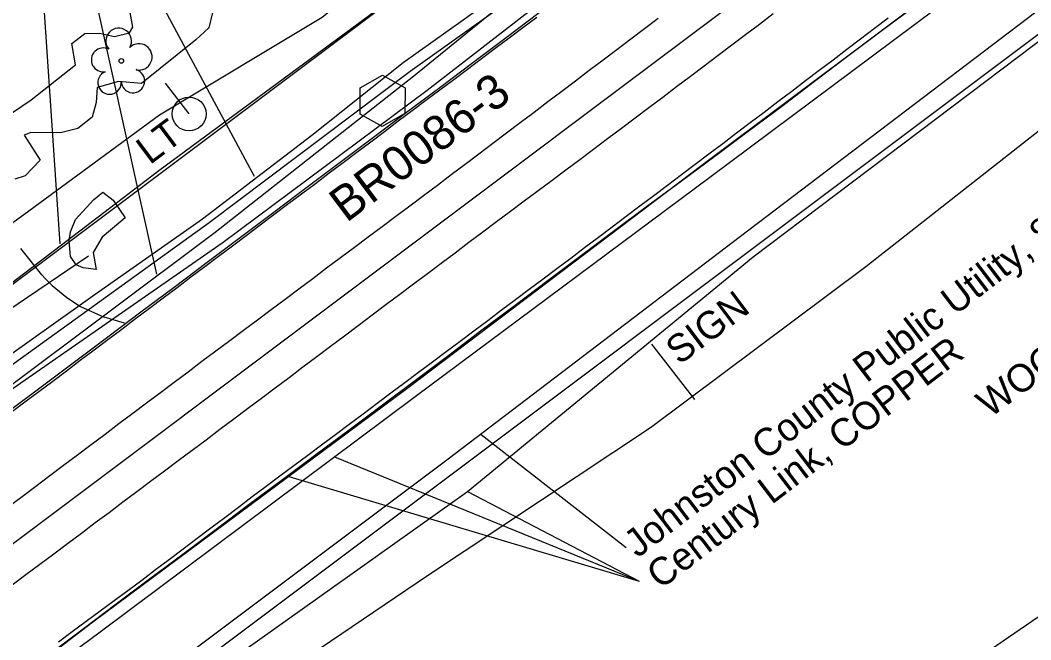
# Model space of a CAD drawing. Extents: x 2186615 to 2188822, y 629899 to 631820.
# Drawn here: x 2188283 to 2188429.1, y 631223.1 to 631312.5 of the extents above; entities that cross this region are included whole.
import ezdxf

# ---------------------------------------------------------------- set-up
doc = ezdxf.new("R2010")
doc.units = 0
for name, color, linetype in [('CTL Primary Horizontal and Vertical CELL', 7, 'Continuous'), ('CTL Primary Horizontal and Vertical Text', 7, 'Continuous'), ('Exist Horizontal Alignment', 7, 'Continuous'), ('Exist Other Culture Area Outline', 7, 'Continuous'), ('Exist Other Culture Sign', 7, 'Continuous'), ('Exist Other Culture Sign Text', 7, 'Continuous'), ('Exist Right of Way Line', 7, 'Continuous'), ('Exist Roads EOP', 7, 'Continuous'), ('Exist Roads EOT', 7, 'Continuous'), ('Exist Roads Soil', 7, 'Continuous'), ('Exist Structure Minor Pipes RCP 18 Inch', 7, 'Continuous'), ('Exist Utilities Gas UG Line SUE LOS B', 7, 'Continuous'), ('Exist Utilities Gas UG Line SUE LOS B Leader', 7, 'Continuous'), ('Exist Utilities Power Pole CELL', 7, 'Continuous'), ('Exist Utilities Power Pole Text', 7, 'Continuous'), ('Exist Utilities Sanitary Sewer Forced Main SUE LOS B', 7, 'Continuous'), ('Exist Utilities Sanitary Sewer Forced Main SUE LOS B Leader', 7, 'Continuous'), ('Exist Utilities Sanitary Sewer Forced Main SUE LOS B Text', 7, 'Continuous'), ('Exist Utilities Telephone UG Cable SUE LOS C', 7, 'Continuous'), ('Exist Utilities Telephone UG Cable SUE LOS C Leader', 7, 'Continuous'), ('Exist Utilities Telephone UG Cable SUE LOS C Text', 7, 'Continuous'), ('Exist Utilities Telephone UG FO SUE LOS B', 7, 'Continuous'), ('Exist Utilities Telephone UG FO SUE LOS B Leader', 7, 'Continuous'), ('Exist Utilities Water UG Line SUE LOS B', 7, 'Continuous'), ('Exist Utilities Water UG Line SUE LOS B Leader', 7, 'Continuous'), ('Exist Vegetation Hedge Row', 7, 'Continuous'), ('Exist Vegetation Tree CELL', 7, 'Continuous'), ('Exist Vegetation Woods Line', 7, 'Continuous'), ('Exist Vegetation Woods Line Text', 7, 'Continuous')]:
    doc.layers.add(name, color=color, linetype=linetype)

msp = doc.modelspace()

# ---------------------------------------------------------------- linework, layer by layer
at = {"layer": 'CTL Primary Horizontal and Vertical CELL'}
msp.add_line((2188335.41, 631300.89), (2188335.41, 631300.89), dxfattribs=at)
msp.add_lwpolyline([(2188332.17, 631302.76), (2188335.42, 631304.58), (2188338.67, 631302.79), (2188338.62, 631299.06), (2188335.37, 631297.18), (2188332.17, 631298.99)], close=True, dxfattribs=at)
at = {"layer": 'Exist Horizontal Alignment'}
msp.add_line((2187136.41, 630378.11), (2188520.86, 631416.04), dxfattribs=at)
at = {"layer": 'Exist Other Culture Area Outline'}
msp.add_lwpolyline([(2188291.05, 631283.75), (2188293.63, 631286.62), (2188295, 631287.71), (2188296.46, 631286.56), (2188298.22, 631283.98), (2188294.91, 631281.2), (2188293.6, 631278.98), (2188294.02, 631276.56), (2188292.16, 631276.76), (2188291.14, 631277.22), (2188290.31, 631278.41), (2188290.14, 631280.66), (2188290.34, 631282), (2188291.05, 631283.75)], dxfattribs=at)
at = {"layer": 'Exist Other Culture Sign'}
msp.add_line((2188374.26, 631265.78), (2188380.47, 631257.75), dxfattribs=at)
at = {"layer": 'Exist Right of Way Line'}
for p, q in [((2187118.41, 630402.11), (2188502.83, 631440.02)), ((2187154.4, 630354.1), (2188538.85, 631392.04))]:
    msp.add_line(p, q, dxfattribs=at)
at = {"layer": 'Exist Roads EOP'}
for points in [[(2188281.29, 631256.01), (2188286.1, 631259.61), (2188290.9, 631263.21), (2188295.7, 631266.81), (2188300.49, 631270.41), (2188305.29, 631274.01), (2188310.09, 631277.62), (2188314.89, 631281.22), (2188319.68, 631284.82), (2188324.48, 631288.43), (2188329.28, 631292.03), (2188334.08, 631295.63), (2188338.87, 631299.24), (2188343.67, 631302.84), (2188348.47, 631306.45), (2188353.26, 631310.05), (2188358.05, 631313.67), (2188362.84, 631317.28), (2188367.63, 631320.9), (2188372.41, 631324.51), (2188377.2, 631328.13), (2188381.99, 631331.74), (2188386.8, 631335.34), (2188391.5, 631338.86)], [(2188412.22, 631314.48), (2188407.4, 631310.9), (2188402.59, 631307.32), (2188397.82, 631303.68), (2188393.07, 631300.02), (2188388.25, 631296.45), (2188383.43, 631292.88), (2188378.6, 631289.31), (2188373.77, 631285.75), (2188368.96, 631282.16), (2188364.16, 631278.56), (2188359.36, 631274.96), (2188354.56, 631271.36), (2188349.77, 631267.76), (2188344.98, 631264.14), (2188340.19, 631260.53), (2188335.39, 631256.93), (2188330.58, 631253.34), (2188325.77, 631249.76), (2188320.96, 631246.17), (2188316.16, 631242.58), (2188311.35, 631238.99), (2188306.54, 631235.4), (2188301.74, 631231.8), (2188296.93, 631228.21), (2188292.13, 631224.61), (2188287.34, 631221)]]:
    msp.add_lwpolyline(points, dxfattribs=at)
at = {"layer": 'Exist Roads EOT'}
for points in [[(2188281.33, 631242.27), (2188283.32, 631243.77), (2188285.32, 631245.27), (2188287.32, 631246.77), (2188289.32, 631248.27), (2188291.32, 631249.77), (2188293.32, 631251.28), (2188295.32, 631252.78), (2188297.32, 631254.28), (2188299.32, 631255.78), (2188301.32, 631257.28), (2188303.32, 631258.78), (2188305.31, 631260.28), (2188307.31, 631261.78), (2188309.32, 631263.28), (2188311.32, 631264.78), (2188313.32, 631266.28), (2188315.32, 631267.77), (2188317.32, 631269.27), (2188319.32, 631270.77), (2188321.33, 631272.26), (2188323.33, 631273.76), (2188325.33, 631275.26), (2188327.33, 631276.76), (2188329.34, 631278.25), (2188331.34, 631279.75), (2188333.34, 631281.25), (2188335.34, 631282.75), (2188337.34, 631284.24), (2188339.34, 631285.74), (2188341.35, 631287.24), (2188343.35, 631288.74), (2188345.34, 631290.24), (2188347.34, 631291.75), (2188349.33, 631293.26), (2188351.33, 631294.76), (2188353.32, 631296.27), (2188355.32, 631297.78), (2188357.31, 631299.28), (2188359.31, 631300.79), (2188361.3, 631302.3), (2188363.3, 631303.8), (2188365.29, 631305.31), (2188367.28, 631306.82), (2188369.28, 631308.33), (2188371.27, 631309.83), (2188373.27, 631311.34), (2188375.26, 631312.84)], [(2188281.74, 631255.92), (2188283.74, 631257.43), (2188285.74, 631258.93), (2188287.74, 631260.43), (2188289.73, 631261.93), (2188291.73, 631263.44), (2188293.73, 631264.94), (2188295.73, 631266.44), (2188297.73, 631267.94), (2188299.72, 631269.45), (2188301.72, 631270.95), (2188303.72, 631272.45), (2188305.72, 631273.95), (2188307.72, 631275.46), (2188309.71, 631276.96), (2188311.71, 631278.46), (2188313.71, 631279.96), (2188315.71, 631281.46), (2188317.71, 631282.97), (2188319.71, 631284.47), (2188321.7, 631285.97), (2188323.7, 631287.47), (2188325.7, 631288.97), (2188327.7, 631290.48), (2188329.7, 631291.98), (2188331.7, 631293.48), (2188333.7, 631294.98), (2188335.69, 631296.48), (2188337.69, 631297.99), (2188339.69, 631299.49), (2188341.69, 631300.99), (2188343.69, 631302.49), (2188345.69, 631303.99), (2188347.69, 631305.49), (2188349.69, 631306.99), (2188351.69, 631308.49), (2188353.69, 631309.99), (2188355.69, 631311.49), (2188357.69, 631312.99)], [(2188281.88, 631230.99), (2188283.88, 631232.49), (2188285.88, 631233.99), (2188287.89, 631235.48), (2188289.89, 631236.98), (2188291.89, 631238.48), (2188293.89, 631239.98), (2188295.89, 631241.47), (2188297.89, 631242.97), (2188299.9, 631244.47), (2188301.9, 631245.97), (2188303.9, 631247.47), (2188305.9, 631248.96), (2188307.9, 631250.46), (2188309.9, 631251.96), (2188311.9, 631253.46), (2188313.91, 631254.96), (2188315.91, 631256.45), (2188317.91, 631257.96), (2188319.9, 631259.46), (2188321.9, 631260.96), (2188323.9, 631262.46), (2188325.9, 631263.96), (2188327.9, 631265.46), (2188329.9, 631266.97), (2188331.9, 631268.47), (2188333.89, 631269.97), (2188335.89, 631271.47), (2188337.89, 631272.97), (2188339.89, 631274.48), (2188341.89, 631275.98), (2188343.89, 631277.47), (2188345.89, 631278.97), (2188347.89, 631280.47), (2188349.9, 631281.96), (2188351.9, 631283.46), (2188353.9, 631284.96), (2188355.9, 631286.46), (2188357.91, 631287.95), (2188359.91, 631289.45), (2188361.91, 631290.95), (2188363.91, 631292.44), (2188365.92, 631293.94), (2188367.92, 631295.44), (2188369.92, 631296.94), (2188371.92, 631298.44), (2188373.91, 631299.94), (2188375.91, 631301.45), (2188377.9, 631302.96), (2188379.9, 631304.46), (2188381.89, 631305.97), (2188383.89, 631307.47), (2188385.89, 631308.98), (2188387.88, 631310.48), (2188389.88, 631311.99), (2188391.87, 631313.49)], [(2188408.48, 631312.83), (2188406.49, 631311.32), (2188404.5, 631309.81), (2188402.5, 631308.3), (2188400.51, 631306.79), (2188398.52, 631305.28), (2188396.53, 631303.77), (2188394.54, 631302.26), (2188392.55, 631300.74), (2188390.56, 631299.23), (2188388.56, 631297.72), (2188386.57, 631296.22), (2188384.57, 631294.71), (2188382.58, 631293.21), (2188380.58, 631291.7), (2188378.59, 631290.2), (2188376.59, 631288.69), (2188374.6, 631287.18), (2188372.6, 631285.68), (2188370.6, 631284.17), (2188368.61, 631282.67), (2188366.61, 631281.16), (2188364.62, 631279.66), (2188362.62, 631278.15), (2188360.62, 631276.65), (2188358.62, 631275.15), (2188356.62, 631273.65), (2188354.62, 631272.15), (2188352.62, 631270.65), (2188350.62, 631269.15), (2188348.62, 631267.65), (2188346.62, 631266.15), (2188344.62, 631264.65), (2188342.62, 631263.15), (2188340.62, 631261.65), (2188338.62, 631260.16), (2188336.61, 631258.66), (2188334.61, 631257.17), (2188332.61, 631255.67), (2188330.6, 631254.17), (2188328.6, 631252.68), (2188326.6, 631251.18), (2188324.6, 631249.69), (2188322.59, 631248.19), (2188320.59, 631246.69), (2188318.59, 631245.19), (2188316.59, 631243.69), (2188314.6, 631242.19), (2188312.6, 631240.68), (2188310.61, 631239.17), (2188308.61, 631237.67), (2188306.62, 631236.16), (2188304.62, 631234.65), (2188302.62, 631233.15), (2188300.63, 631231.65), (2188298.62, 631230.16), (2188296.61, 631228.67), (2188294.6, 631227.18), (2188292.59, 631225.7), (2188290.58, 631224.21), (2188288.57, 631222.72)]]:
    msp.add_lwpolyline(points, dxfattribs=at)
at = {"layer": 'Exist Roads Soil'}
for points in [[(2188286.65, 631275.23), (2188286.18, 631275.75), (2188283.12, 631279.56)], [(2188286.65, 631275.23), (2188287.68, 631274.25), (2188289.79, 631272.52), (2188291.78, 631271.19), (2188295.18, 631269.64)], [(2188298.13, 631268.79), (2188295.18, 631269.64)]]:
    msp.add_lwpolyline(points, dxfattribs=at)
at = {"layer": 'Exist Structure Minor Pipes RCP 18 Inch'}
msp.add_line((2188232.7, 631237.84), (2188292.92, 631278.53), dxfattribs=at)
at = {"layer": 'Exist Utilities Gas UG Line SUE LOS B'}
msp.add_lwpolyline([(2188219.39, 631219.84), (2188231.62, 631228.2), (2188246.17, 631238.93), (2188255.42, 631245.33), (2188268.48, 631254.78), (2188278.59, 631262.16), (2188293.89, 631272.96), (2188309.4, 631283.84), (2188325.21, 631295.95), (2188338.4, 631306.43), (2188349.22, 631314.15), (2188361.2, 631323.18), (2188372.45, 631332.07), (2188381.36, 631339.98), (2188392.05, 631352.12), (2188396.89, 631358.2), (2188400.9, 631362.5), (2188409.32, 631368.76), (2188417.18, 631375.21), (2188429.81, 631386.38)], dxfattribs=at)
at = {"layer": 'Exist Utilities Gas UG Line SUE LOS B Leader'}
msp.add_line((2188316.89, 631289.98), (2188292.6, 631335.2), dxfattribs=at)
at = {"layer": 'Exist Utilities Power Pole CELL'}
for q in [(2188304.05, 631303.47), (2188307.45, 631299)]:
    msp.add_line((2188307.45, 631299), q, dxfattribs=at)
msp.add_circle((2188307.45, 631299), 2.45, dxfattribs=at)
at = {"layer": 'Exist Utilities Sanitary Sewer Forced Main SUE LOS B'}
msp.add_lwpolyline([(2188052.08, 631035.89), (2188074.5, 631052.61), (2188093.79, 631066.37), (2188121.43, 631086.62), (2188146.17, 631105.29), (2188183, 631130.32), (2188212.25, 631151.9), (2188236.06, 631169.55), (2188274.9, 631197.79), (2188300.59, 631215.98), (2188344.72, 631249.04), (2188387.13, 631281.33), (2188437.44, 631319.58), (2188480.75, 631351.94), (2188530.77, 631388.8), (2188537.37, 631394.07)], dxfattribs=at)
at = {"layer": 'Exist Utilities Sanitary Sewer Forced Main SUE LOS B Leader'}
msp.add_line((2188349.66, 631252.69), (2188370.64, 631236.4), dxfattribs=at)
at = {"layer": 'Exist Utilities Telephone UG Cable SUE LOS C'}
for points in [[(2188096.88, 630993.34), (2188080.22, 631017.51), (2188064.37, 631042.87), (2188062.98, 631045.24), (2188062.65, 631047.71), (2188067.09, 631054.3), (2188068.63, 631056.84), (2188089.09, 631072.74), (2188116.44, 631092.81), (2188141.03, 631110.94), (2188178.22, 631138.01), (2188229.96, 631175.9), (2188269.4, 631205.59), (2188294.58, 631224.2), (2188340.11, 631258.2), (2188382.72, 631289.85), (2188432.93, 631327.36), (2188477.32, 631360.56), (2188524.82, 631398.08), (2188530.94, 631402.62)], [(2188239.88, 631089.23), (2188209.7, 631139.17), (2188205.31, 631145.33), (2188202.92, 631147.6), (2188200.81, 631153.01), (2188202.37, 631156.1), (2188209.69, 631162.82), (2188228.85, 631177.06), (2188268.68, 631206.68), (2188293.54, 631225.66), (2188339.11, 631259.48), (2188381.57, 631291.6), (2188431.82, 631329.3), (2188475.74, 631362.76), (2188523.99, 631399.21), (2188530.06, 631403.8)], [(2188312.37, 631280.51), (2188341.87, 631302.43), (2188368.35, 631323.01), (2188385.25, 631335.41), (2188398.42, 631345.26), (2188424.55, 631364.83), (2188476.35, 631403.47)], [(2188094.37, 630991.41), (2188096.88, 630993.34), (2188087.79, 631026.43), (2188086.82, 631054.16), (2188087.06, 631058.84), (2188088.93, 631062.35), (2188093.27, 631066.84), (2188121.22, 631086.85), (2188145.88, 631105.9), (2188182.55, 631131.21), (2188212.13, 631152.41), (2188236.63, 631168.55), (2188279.23, 631192.06), (2188292.43, 631201.57), (2188302.49, 631212.36), (2188347.67, 631244.49), (2188388.98, 631278.39), (2188439.32, 631316.4), (2188482.92, 631349.33), (2188532.32, 631387.1), (2188539.16, 631391.7)], [(2188310.34, 631283.34), (2188339.41, 631305.19), (2188367.17, 631324.97), (2188382.91, 631337.59), (2188408.07, 631361.6)], [(2188214.19, 631233.71), (2188214.21, 631236.64), (2188215.1, 631239.68), (2188225.32, 631247.53), (2188241.06, 631256.41), (2188259.35, 631266.95), (2188283.55, 631284.49), (2188303.17, 631298.86), (2188326.67, 631313), (2188359.63, 631339.91)], [(2188214.19, 631233.71), (2188224.61, 631226.53), (2188230.77, 631229.27), (2188255.03, 631245.94), (2188279.19, 631260.88), (2188310.34, 631283.34)], [(2188214.19, 631233.71), (2188223.22, 631223.19), (2188223.22, 631223.19), (2188232.86, 631227.26), (2188257.42, 631242.88), (2188270.4, 631252.69), (2188280.92, 631258.65), (2188312.37, 631280.51)]]:
    msp.add_lwpolyline(points, dxfattribs=at)
at = {"layer": 'Exist Utilities Telephone UG Cable SUE LOS C Leader'}
for p in [(2188328.49, 631249.49), (2188321.85, 631246.64), (2188347.67, 631244.49)]:
    msp.add_line(p, (2188372.5, 631231.51), dxfattribs=at)
at = {"layer": 'Exist Utilities Telephone UG FO SUE LOS B'}
for points in [[(2188303.07, 631290.83), (2188335.53, 631314.77), (2188356.73, 631330.39), (2188376.84, 631345.11), (2188395.22, 631359.35), (2188416.54, 631375.89), (2188457.16, 631405.12)], [(2187859.07, 630951.55), (2187882.76, 630968.07), (2187903.06, 630983.05), (2187928.09, 631001.38), (2187948.02, 631018.93), (2187983.82, 631042.28), (2188016.23, 631068.08), (2188049.6, 631091.76), (2188063.06, 631102.31), (2188071.06, 631108.58), (2188069.02, 631112.49), (2188069.37, 631119.05), (2188075.07, 631125.87), (2188092.55, 631139.53), (2188117.88, 631159.65), (2188156.33, 631187.11), (2188185.96, 631206.22), (2188210.21, 631221.29), (2188233.48, 631238.15), (2188251.53, 631251.3), (2188274.73, 631269.24), (2188303.07, 631290.83)]]:
    msp.add_lwpolyline(points, dxfattribs=at)
at = {"layer": 'Exist Utilities Telephone UG FO SUE LOS B Leader'}
msp.add_line((2188288.8, 631280.26), (2188284.46, 631344.66), dxfattribs=at)
at = {"layer": 'Exist Utilities Water UG Line SUE LOS B'}
for points in [[(2188311.2, 631281.93), (2188339.94, 631304.52), (2188359.74, 631320.63), (2188366.75, 631325.42), (2188378.12, 631334.45), (2188382.61, 631338.14), (2188396.4, 631348.39), (2188421.73, 631367.94), (2188462.18, 631399.29)], [(2187858.58, 630939.62), (2187877.52, 630954.54), (2187897.98, 630970.72), (2187926.28, 630993.39), (2187953.07, 631014.11), (2187986.18, 631039.09), (2188018.97, 631064.16), (2188052.07, 631088.62), (2188105.21, 631128.41), (2188127.75, 631145.3), (2188164.18, 631174.44), (2188192.98, 631196.26), (2188209.23, 631208.45), (2188231.7, 631224.75), (2188257.48, 631242.51), (2188270.74, 631252.18), (2188280.66, 631259.06), (2188311.2, 631281.93)]]:
    msp.add_lwpolyline(points, dxfattribs=at)
at = {"layer": 'Exist Utilities Water UG Line SUE LOS B Leader'}
msp.add_line((2188302.8, 631275.85), (2188288.43, 631340.62), dxfattribs=at)
at = {"layer": 'Exist Vegetation Hedge Row'}
for points in [[(2188280.75, 631298.37), (2188284.61, 631301.05), (2188291.02, 631306.11), (2188290.53, 631309.2), (2188292.38, 631310.61), (2188294.52, 631310.68), (2188296.69, 631310.2), (2188298.86, 631310.7), (2188299.34, 631311.54), (2188298.74, 631314.71)], [(2188310.84, 631313.66), (2188310.32, 631311.46), (2188308.41, 631309.71), (2188300.6, 631303.41), (2188297.24, 631303.67), (2188294.18, 631302.82), (2188294.02, 631300.66), (2188293.45, 631298.53), (2188291.39, 631296.9), (2188288.88, 631296.26), (2188284.6, 631296.3), (2188283.62, 631295.93), (2188285.95, 631292.32)], [(2188285.95, 631292.32), (2188283.78, 631290.08), (2188282.29, 631289.6)]]:
    msp.add_lwpolyline(points, dxfattribs=at)
at = {"layer": 'Exist Vegetation Tree CELL'}
msp.add_line((2188297.66, 631306.66), (2188297.66, 631306.66), dxfattribs=at)
msp.add_circle((2188297.66, 631306.66), 0.326, dxfattribs=at)
for centre, radius, start, end in [((2188297.28, 631309.53), 1.86, 330.1651, 219.7134), ((2188300.21, 631307.24), 1.9, 257.1011, 134.1999), ((2188295.06, 631306.81), 1.73, 62.6636, 279.3457), ((2188295.96, 631303.53), 1.69, 111.5671, 6.231), ((2188299.34, 631303.76), 1.7, 181.2822, 74.56)]:
    msp.add_arc(centre, radius, start, end, dxfattribs=at)
at = {"layer": 'Exist Vegetation Woods Line'}
for points in [[(2188405.25, 631276.99), (2188452.97, 631314.41), (2188499.21, 631349.02), (2188513.85, 631326.63), (2188524.54, 631307.43), (2188525.07, 631303.42)], [(2187900, 630901.47), (2187930.95, 630926.02), (2187966.57, 630951.75), (2187999.62, 630976.07), (2188035.07, 631001.76), (2188066.4, 631024.95), (2188104.74, 631054.06), (2188133.99, 631077.57), (2188163.27, 631099.35), (2188198, 631125.47), (2188236.07, 631154.15), (2188273.27, 631182), (2188303.14, 631206.11), (2188341.9, 631232.33), (2188374.15, 631253.71), (2188405.25, 631276.99)], [(2188440.29, 631233.26), (2188396.29, 631203.13), (2188336.81, 631162.74)]]:
    msp.add_lwpolyline(points, dxfattribs=at)

# ---------------------------------------------------------------- texts
at = {"layer": 'CTL Primary Horizontal and Vertical Text'}
msp.add_text('BR0086-3', height=5, rotation=36.8593, dxfattribs=at).set_placement((2188330.19, 631283.21))
at = {"layer": 'Exist Other Culture Sign Text'}
msp.add_text('SIGN', height=4, rotation=36.8593, dxfattribs=at).set_placement((2188378.29, 631262.67))
at = {"layer": 'Exist Utilities Power Pole Text'}
msp.add_text('LT', height=4, rotation=36.8593, dxfattribs=at).set_placement((2188301.78, 631291.58))
at = {"layer": 'Exist Utilities Sanitary Sewer Forced Main SUE LOS B Text'}
msp.add_text('Johnston County Public Utility, 8 ", PVC', height=4, rotation=37.3672, dxfattribs=at).set_placement((2188372.27, 631234.8))
at = {"layer": 'Exist Utilities Telephone UG Cable SUE LOS C Text'}
msp.add_text('Century Link, COPPER', height=4, rotation=37.3672, dxfattribs=at).set_placement((2188375.56, 631230.24))
at = {"layer": 'Exist Vegetation Woods Line Text'}
msp.add_text('WOODED', height=4, rotation=36.8593, dxfattribs=at).set_placement((2188423.2, 631255.03))

doc.saveas('drawing.dxf')
